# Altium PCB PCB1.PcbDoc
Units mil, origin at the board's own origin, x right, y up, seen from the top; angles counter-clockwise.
Board outline 1059 x 802 mil, 2 copper layers (Top Layer, Bottom Layer); 11 components, 9 nets, 42 pads, 0 vias.
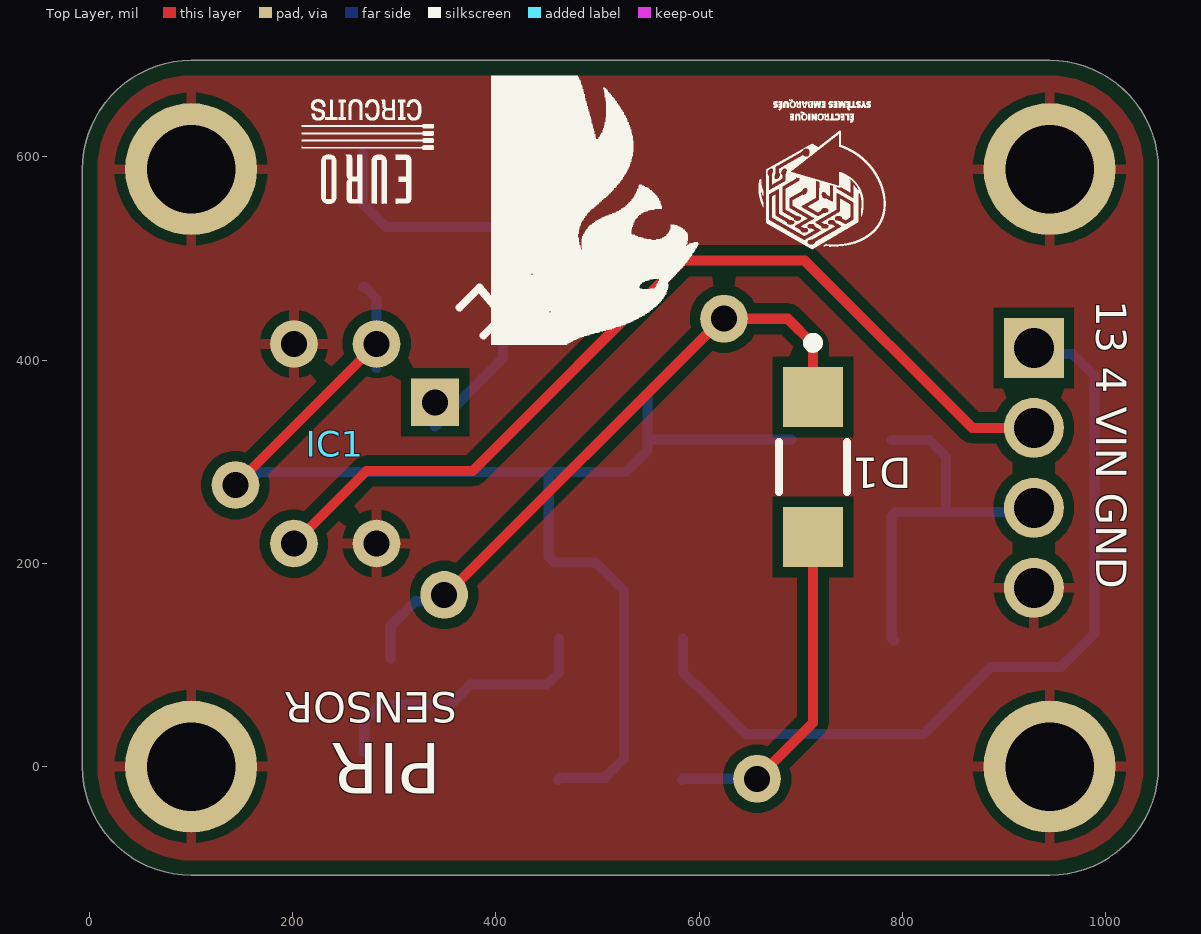
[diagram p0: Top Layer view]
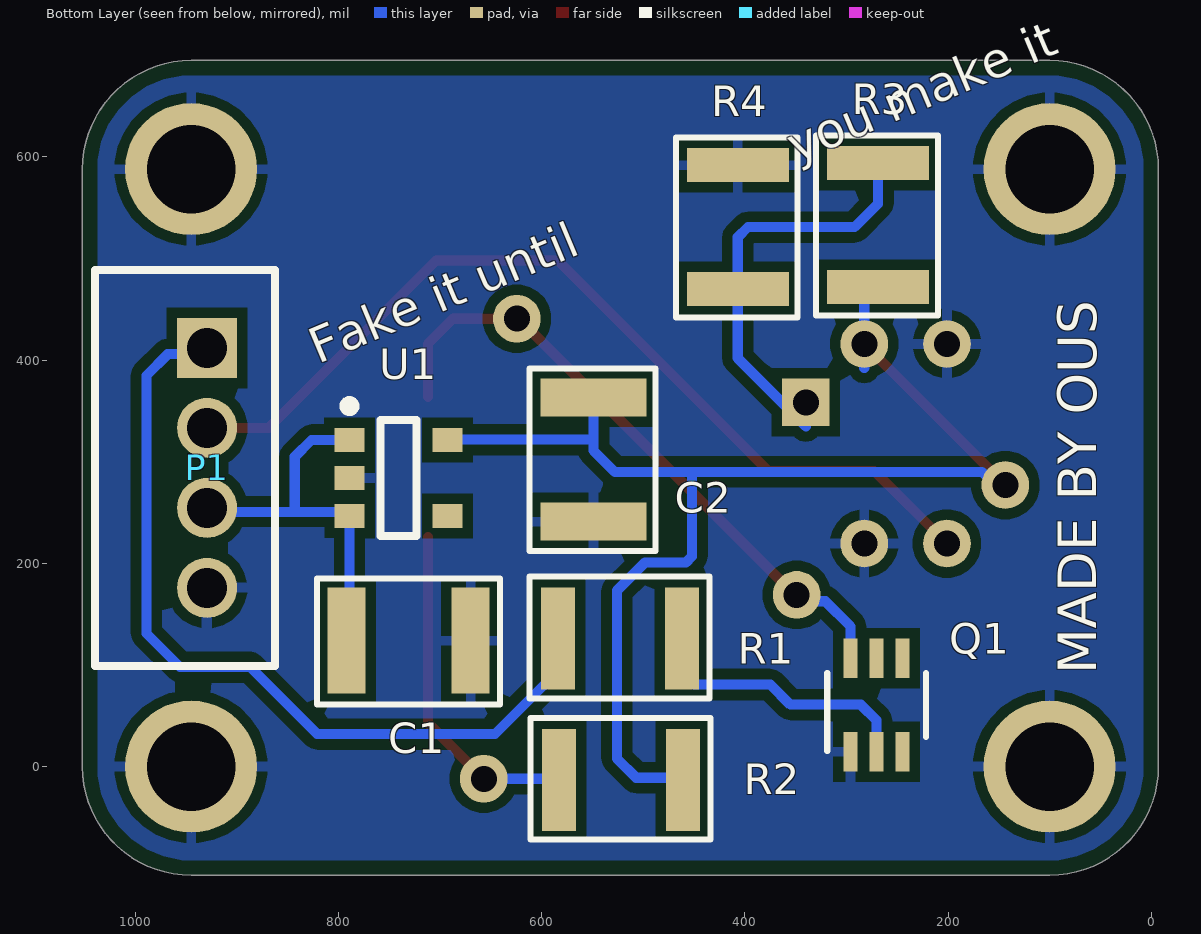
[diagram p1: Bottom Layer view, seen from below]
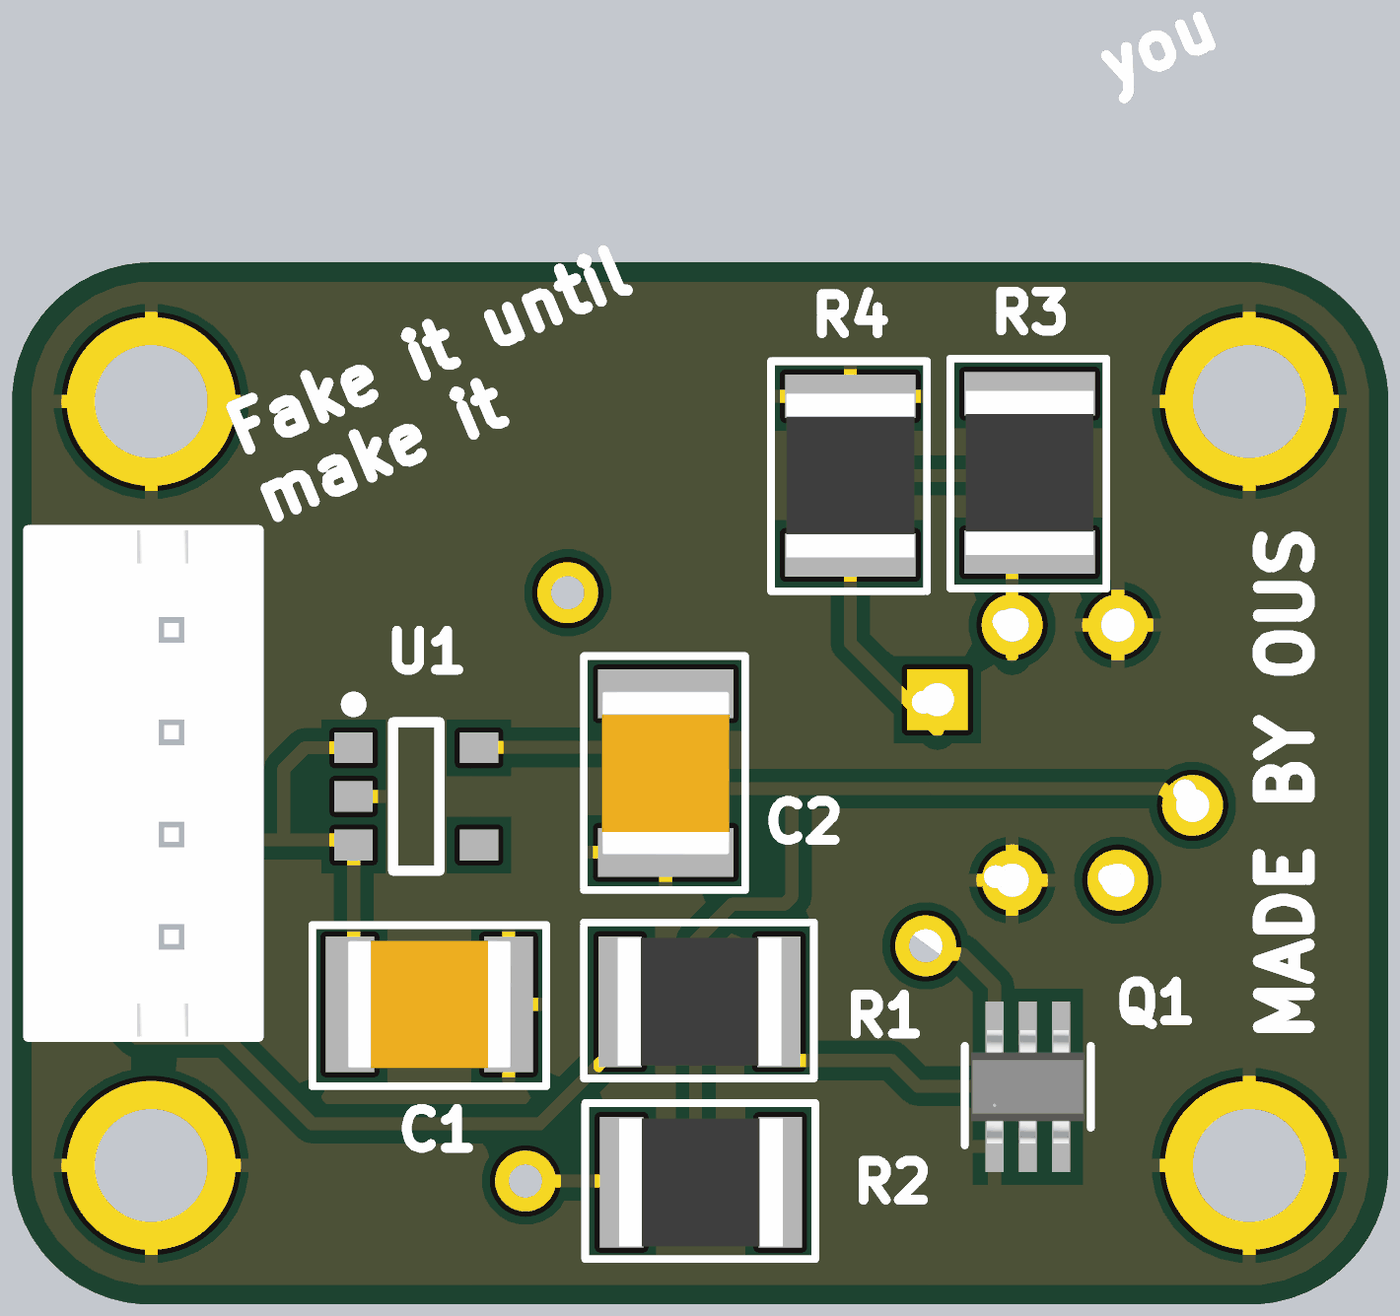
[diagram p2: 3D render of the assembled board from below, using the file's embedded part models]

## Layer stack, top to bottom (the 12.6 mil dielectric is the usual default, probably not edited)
Top Solder: solder mask 0.4, Solder Resist, Dk 3.5
Top Layer: signal copper 1.4
Dielectric 1: dielectric 12.6, FR-4, Dk 4.8
Bottom Layer: signal copper 1.4
Bottom Solder: solder mask 0.4, Solder Resist, Dk 3.5

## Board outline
-7,0 -7,588 cw(c100,588) 100,695 945,695 cw(c945,588) 1052,588 1052,0 cw(c945,0) 945,-107 100,-107 cw(c100,0)

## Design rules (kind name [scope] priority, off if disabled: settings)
Clearance [All] p1: gap=10 ignorepadtopadclearanceinfootprint=FALSE
PolygonConnect [All] p1: connectstyle=Relief reliefconductorwidth=10 reliefentries=4 polygonreliefangle="90 Angle" airgapwidth=10
RoutingVias [All] p1: holewidth=28 width=50 viastyle="Through Hole" minholewidth=28 minwidth=50 maxholewidth=28 maxwidth=50
SolderMaskExpansion [All] p1: expansion=4 istentingtop=FALSE
SupplyNets "Schematic Supply Nets_1" [InNet('VCC')] p1: voltage=0.000
SupplyNets "Schematic Supply Nets" [InNet('GND')] p2: voltage=0.000
Width [All] p1: maxlimit=10 minlimit=10 preferedwidth=10
30 further rules are at their usual default settings.

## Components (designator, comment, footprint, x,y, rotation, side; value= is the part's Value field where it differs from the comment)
C1 "Val?" 1206-C 731,124 r0 bottom
C2 "Val?" 1206-C 549,302 r90 bottom
D1 "LTST-C150KSKT" FP-LTST-C150KSKT-MFG 712,295 r270 top
IC1 "BS612" BS612 340,358.44 r90 top
P1 "B4B-PH-K-S(LF)(SN)" JST-B4B-PH-K-S_V 951,294 r270 bottom
Q1 "BSS138PS,115" SC-88_SOT363_NEX-M 270.41,60.5 r90 bottom
R1 "Val?" 1206-R 523,126 r180 bottom
R2 "Val?" 1206-R 522,-13 r180 bottom
R3 "Val?" 1206-R 269,533 r90 bottom
R4 "Val?" 1206-R 407,531 r90 bottom
U1 "ADP150AUJZ-3.3-R7" ADI-UJ-5_L 741,284 r180 bottom

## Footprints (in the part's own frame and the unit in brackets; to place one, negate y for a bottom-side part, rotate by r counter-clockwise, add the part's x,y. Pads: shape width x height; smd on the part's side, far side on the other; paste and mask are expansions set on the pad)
1206-C [mm] "Chip Capacitor, 2-Leads, Body 3,20x2,50mm, IPC Medium Density"
  rect 0.95x2.65 smd: 1(-1.55,0) 2(1.55,0)
  silkscreen extent -2.29,-1.55 2.29,1.6, body extent -1.6,-1.25 1.6,1.25, height 0.55
1206-R [mm] "Chip Resistor, 2-Leads, Body 3,20x2,50mm, IPC Medium Density"
  rect 0.85x2.55 smd: 1(-1.55,0) 2(1.55,0)
  silkscreen extent -2.26,-1.5 2.24,1.55, body extent -1.6,-1.25 1.6,1.25, height 0.55
ADI-UJ-5_L [mm] "SOT23, 5-Leads, Body 2.9x1.6mm, Pitch 0.95mm, IPC High Density"
  rect 0.75x0.6 smd: 1(-1.225,0.95) 2(-1.225,0) 3(-1.225,-0.95) 4(1.225,-0.95) 5(1.225,0.95)
  silkscreen extent -1.35,-1.45 0.45,1.92, body extent -0.8,-1.45 0.8,1.45, height 1
BS612 [mm]
  rect 1.192x1.192 hole 0.65: 1(0,0)
  round 1.192 hole 0.65: 2(1.461,1.461) 3(1.461,3.527) 4(-2.066,4.988) 5(-3.528,3.527) 6(-3.528,1.461)
  silkscreen extent 1.67,-1.71 2.87,-0.61, body extent -5.55,-2.3 3.55,6.8, height 5.19
FP-LTST-C150KSKT-MFG [mm]
  rect 1.5x1.5 smd paste+0 mask+0: 1(-1.75,0) 2(1.75,0)
  silkscreen extent -3.22,-0.85 0.63,0.85, body extent -2.6,-0.95 2.6,0.95, height 0.25
JST-B4B-PH-K-S_V [mm] "Connector, 4-Leads, Body 9.9x4.5mm, Pitch 2mm"
  rect 1.5x1.5 hole 1: 1(-3,0.55)
  round 1.5 hole 1: 2(-1,0.55) 3(1,0.55) 4(3,0.55)
  silkscreen extent -4.95,-2.25 4.95,2.25, body extent -4.95,-2.25 4.95,2.25, height 6
SC-88_SOT363_NEX-M [mil]
  rect 39x14 smd paste+0 mask+0: 1(-46,25.59) 2(-46,0) 3(-46,-25.59) 4(46,-25.59) 5(46,0) 6(46,25.59)
  silkscreen extent -45,-48 32,48, body extent -44,-44 44,44, height 43

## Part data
C1 C2: library part Capacitor-NP
D1: library part CMP-2000-06618-2, "LED YELLOW CLEAR 1206 SMD", Case Code (Imperial)=1206, Case Code (Metric)=3216, Color=Yellow, Forward Current=30mA, Forward Voltage=2.4V, Lens Color=Colorless, Max Operating Temperature=85°C, Min Operating Temperature=-55°C, Package Quantity=1, Power Dissipation=75mW, Reverse Voltage=5V, Test Current=20mA
IC1: "Integrated Circuit", Manufacturer_Name=Adafruit, Manufacturer_Part_Number=5578, Mouser Part Number=485-5578
P1: library part CMP-2000-05165-1, "Male Header, Pitch 2 mm, 1 x 4 Position, Height 6 mm, Tail Length 3.4 mm, -25 to 85 degC, RoHS, Bulk", Manufacturer=JST
Q1: "Description", Manufacturer_Name=Nexperia
R1 R2 R3 R4: library part Resistor
U1: library part CMP-0786-00394-1, "Ultralow Noise, 150 mA CMOS Linear Regulator, 2.2 to 5.5 V Vin, 3.3 V Vout, Industrial, 5-pin SOT23 (UJ-5), Reel", Manufacturer="Analog Devices", Preset Vout Values (V)=3.3, Supply Current IGND @ Small Load=10uA

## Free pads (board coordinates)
  round 130 hole 87: 5(100,0) 5(100,588) 5(945,0) 5(945,588)
  round 46.93 hole 25.59: 6(349,169) 6(624.45,440.78) 6(657,-12)

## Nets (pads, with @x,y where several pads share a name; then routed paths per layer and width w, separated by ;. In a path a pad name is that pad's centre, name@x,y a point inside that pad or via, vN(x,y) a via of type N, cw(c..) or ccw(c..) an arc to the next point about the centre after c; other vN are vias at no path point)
GND: C1.1 C2.1 IC1.3 IC1.6 P1.4 pad.5 Q1.1 R4.2 U1.2
GPIO4: IC1.5 P1.2 | length 911.7
  Top Layer w10: IC1.5 272.6,291 377,291 584,498 704,498 868.63,333.37 P1.2
GPIO13: P1.1 R1.1 | length 829.4
  Bottom Layer w10: R1.1 584.02,92.54 595.76,80.8 597.2,80.8 646,32 821,32 887,98 956,98 989,131 989,385 968.02,405.98 935.47,405.98 P1.1
NetD1_1: D1.1 pad.6@349,169 pad.6@624.45,440.78 Q1.6 | length 635.3
  Top Layer w10: pad.6@349,169 350.84,169 622.62,440.78 624.45,440.78 687.22,440.78 712,416 D1.1
  Bottom Layer w10: Q1.6 296,138 320.8,162.8 342.8,162.8 pad.6@349,169
NetD1_2: D1.2 pad.6@657,-12 R2.1 | length 335.3
  Top Layer w10: pad.6@657,-12 712,43 D1.2
  Bottom Layer w10: R2.1 584.02,-12 pad.6@657,-12
NetIC1_1: IC1.1 R3.2 R4.1 | length 415.4
  Bottom Layer w10: R3.2@269,604.02 269,554 292,531 397,531 407,521 407,479.98 407,402 IC1.1@340,335
NetQ1_2: Q1.2 R1.2 | length 275.5
  Bottom Layer w10: Q1.2 270.41,45.55 285.86,61 355.22,61 375.02,80.8 450.24,80.8 461.98,92.54 R1.2
VCC: C2.2 IC1.2 IC1.4 R2.2 R3.1 U1.5 | length 1339.6
  Top Layer w10: IC1.4 IC1.2 ; IC1.4@144,271 160.96,271 IC1.4@155.34,265.38
  Bottom Layer w10: IC1.4@143.62,268.08 IC1.4 153.61,277.1 166.51,290 452,290 ; R3.1 270.75,471.98 282.48,460.24 IC1.2 IC1.2@282.48,392.52 ; R2.2 462.98,-11 507,-11 526,8 526,173 498,201 457.86,201 452,206.86 452,290 ; C2.2 549,321 ; U1.5@690.6,321.77 549.77,321.77 549,321 ; 452,290 528,290 549,311 549,321
VSYS_VIN: C1.2 P1.3 U1.1 U1.3 | length 383
  Bottom Layer w10: U1.1 826.6,321.4 843,305 843,252.61 845,250.61 ; C1.2 789.23,126.8 U1.3 793.24,250.61 845,250.61 ; P1.3 925.33,250.61 845,250.61
pads on no net: Q1.3 Q1.4 Q1.5 U1.4

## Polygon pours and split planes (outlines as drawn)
GND on Top Layer "GND_L01_P009" (solid, pour order 9): 8,0 8,588 cw(c100,588) 100,680 945,680 cw(c945,588) 1037,588 1037,0 cw(c945,0) 945,-92 100,-92 cw(c100,0)
GND on Bottom Layer "GND_L02_P008" (solid, pour order 8): 8,0 8,588 cw(c100,588) 100,680 945,680 cw(c945,588) 1037,588 1037,0 cw(c945,0) 945,-92 100,-92 cw(c100,0)

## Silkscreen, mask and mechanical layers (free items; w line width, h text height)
Top Overlay:
  drawing of 53 lines, arcs and shapes, not listed
  text "13 4 VIN GND" at 991,459 h30 r270
  text "SENSOR" at 362,73 h30 r180
  text "PIR" at 346,23 h50 r180
Bottom Overlay:
  text "Fake it until               you make it" at 820,396 h35 r337.2
  text "MADE BY OUS" at 54,91 h38 r270
Dimensions:
  the board outline again, w10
